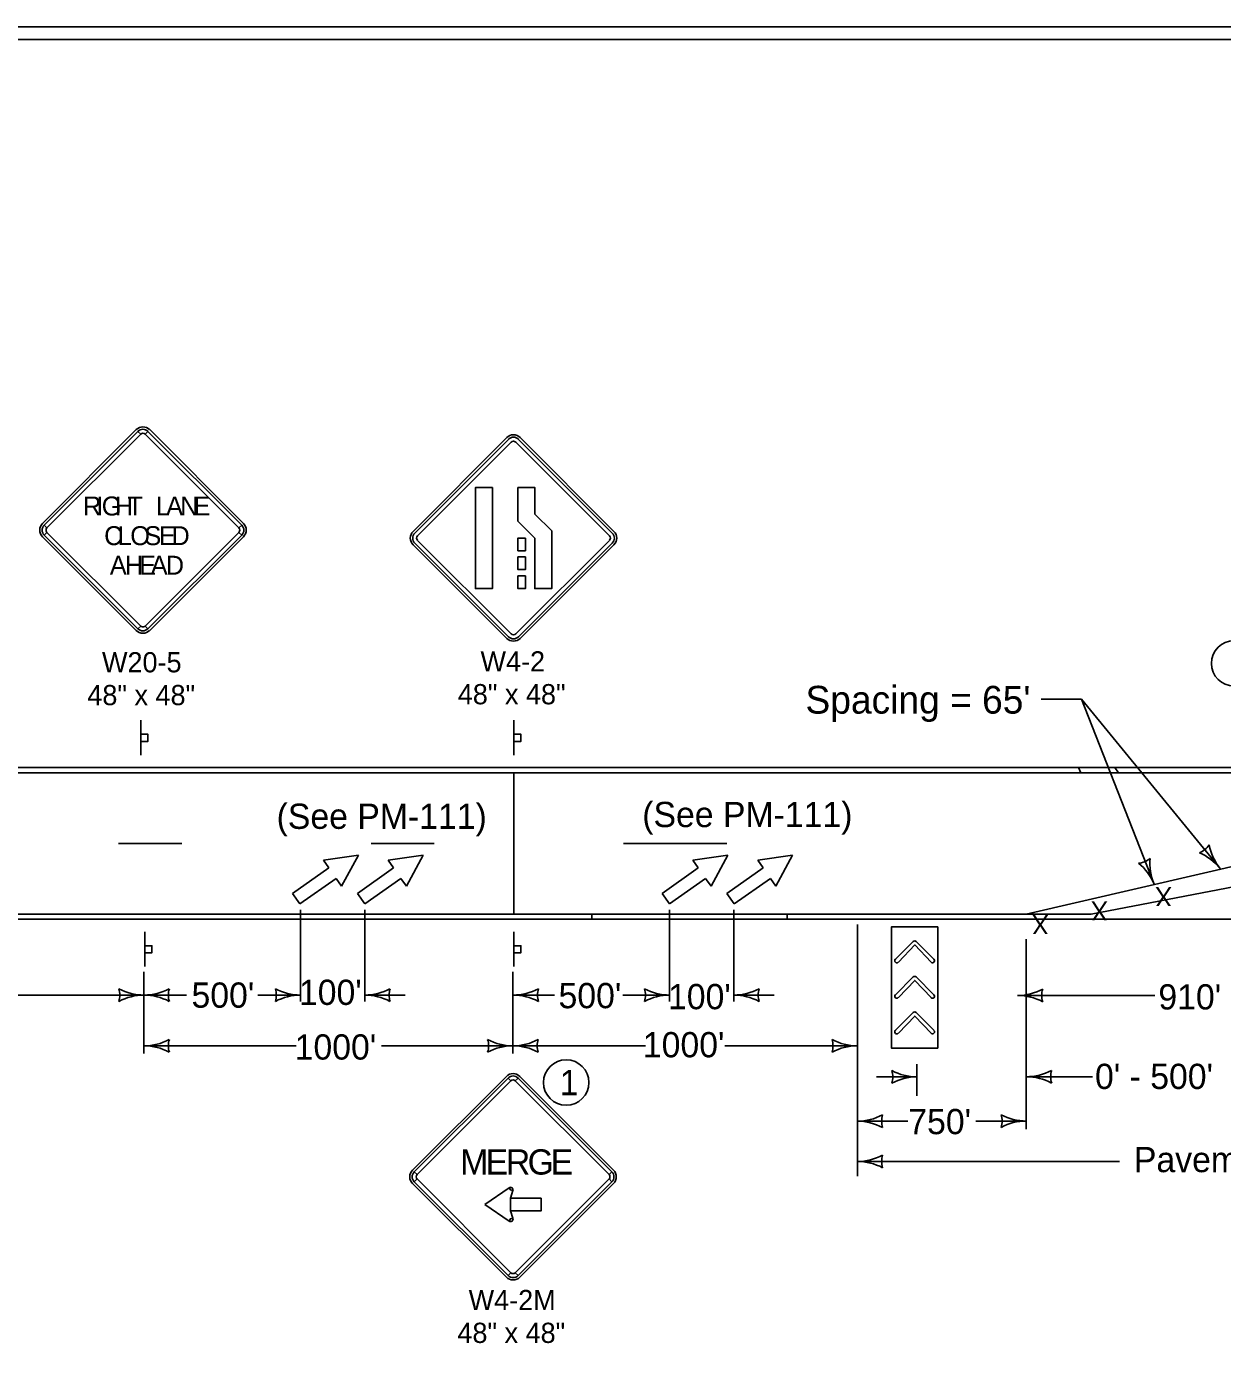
# Model space of a CAD drawing. Extents: x 10133 to 81668, y 4177 to 11018.
# Drawn here: x 28993 to 29940, y 8880 to 9944 of the extents above; entities that cross this region are included whole.
import ezdxf

# ---------------------------------------------------------------- set-up
doc = ezdxf.new("R2010")
doc.units = 0
for name, color, linetype in [('dsnNonPlotable', 7, 'Continuous'), ('dsnStdBlockModified', 7, 'Continuous'), ('dsnStdDimension', 7, 'Continuous'), ('dsnStdLabel', 7, 'Continuous'), ('dsnStdNote', 7, 'Continuous'), ('Level 12', 7, 'Continuous'), ('Level 2', 7, 'Continuous'), ('SheetBorder', 7, 'Continuous')]:
    doc.layers.add(name, color=color, linetype=linetype)

msp = doc.modelspace()

# ---------------------------------------------------------------- linework, layer by layer
at = {"layer": 'dsnNonPlotable'}
for p, q in [((29080, 9624.9), (29005.8, 9550.6)), ((29081.4, 9623.5), (29083.6, 9621.3)), ((29087.1, 9621.3), (29089.3, 9623.5)), ((29164.9, 9550.6), (29090.7, 9624.9)), ((29373.5, 9618.6), (29299.3, 9544.3)), ((29299.3, 9544.3), (29373.5, 9618.6)), ((29374.8, 9617.2), (29300.6, 9543)), ((29302.8, 9540.8), (29377, 9615)), ((29380.6, 9615), (29380.6, 9615)), ((29380.6, 9615), (29454.8, 9540.8)), ((29457, 9543), (29382.8, 9617.2)), ((29458.4, 9544.3), (29384.1, 9618.6)), ((29384.1, 9618.6), (29458.4, 9544.3)), ((29384.1, 9618.6), (29384.1, 9618.6)), ((29009.3, 9547.1), (29007.1, 9549.3)), ((29163.6, 9549.3), (29161.4, 9547.1)), ((29005.8, 9540), (29080, 9465.8)), ((29007.1, 9541.3), (29009.3, 9543.5)), ((29090.7, 9465.8), (29164.9, 9540)), ((29161.4, 9543.5), (29163.6, 9541.3)), ((29377, 9463), (29302.8, 9537.2)), ((29454.8, 9537.2), (29380.6, 9463)), ((29299.3, 9533.7), (29373.5, 9459.5)), ((29373.5, 9459.5), (29299.3, 9533.7)), ((29300.6, 9535), (29374.8, 9460.8)), ((29382.8, 9460.8), (29457, 9535)), ((29384.1, 9459.5), (29458.4, 9533.7)), ((29458.4, 9533.7), (29384.1, 9459.5)), ((29083.6, 9469.3), (29081.4, 9467.1)), ((29089.3, 9467.1), (29087.1, 9469.3)), ((29083.6, 9367.1), (29083.6, 9394.6)), ((29379, 9367.1), (29379, 9394.6)), ((29086.7, 9199.6), (29086.7, 9227.1)), ((29379, 9199.6), (29379, 9227.1)), ((29697.7, 9219.3), (29711.8, 9205.3)), ((29697.7, 9191.3), (29711.8, 9177.2)), ((29697.7, 9163), (29711.8, 9149)), ((29373.2, 9112.5), (29298.9, 9038.2)), ((29374.5, 9111.2), (29376.7, 9109)), ((29380.2, 9109), (29382.4, 9111.2)), ((29458, 9038.2), (29383.8, 9112.5)), ((29302.4, 9034.7), (29300.2, 9036.9)), ((29456.7, 9036.9), (29454.5, 9034.7)), ((29298.9, 9027.6), (29373.2, 8953.4)), ((29300.2, 9029), (29302.4, 9031.2)), ((29383.8, 8953.4), (29458, 9027.6)), ((29454.5, 9031.2), (29456.7, 9029)), ((29375.3, 9024.3), (29376.4, 9022.6)), ((29376.4, 9022.6), (29378.4, 9022)), ((29376.4, 8999.5), (29375.3, 8997.8)), ((29378.4, 9000.1), (29376.4, 8999.5)), ((29376.7, 8956.9), (29374.5, 8954.7)), ((29382.4, 8954.7), (29380.2, 8956.9))]:
    msp.add_line(p, q, dxfattribs=at)
for points in [[(29081.4, 9623.5), (29007.1, 9549.3), (29009.3, 9547.1), (29083.6, 9621.3), (29081.4, 9623.5)], [(29163.6, 9549.3), (29089.3, 9623.5), (29087.1, 9621.3), (29161.4, 9547.1), (29163.6, 9549.3)], [(29362.1, 9579), (29362.1, 9499), (29348.6, 9499), (29348.6, 9579)], [(29395.8, 9557.9), (29409.1, 9544.6), (29409.1, 9499), (29395.6, 9499), (29395.6, 9539), (29382.3, 9552.3), (29382.3, 9579), (29395.8, 9579)], [(29007.1, 9541.3), (29081.4, 9467.1), (29083.6, 9469.3), (29009.3, 9543.5), (29007.1, 9541.3)], [(29089.3, 9467.1), (29163.6, 9541.3), (29161.4, 9543.5), (29087.1, 9469.3), (29089.3, 9467.1)], [(29388.3, 9539), (29382.3, 9539), (29382.3, 9529), (29388.3, 9529)], [(29388.3, 9524), (29382.3, 9524), (29382.3, 9514), (29388.3, 9514)], [(29388.3, 9509), (29382.3, 9509), (29382.3, 9499), (29388.3, 9499)], [(29083.7, 9383.5), (29083.7, 9377.9), (29089.3, 9377.9), (29089.3, 9383.5)], [(29379.1, 9383.5), (29379.1, 9377.9), (29384.7, 9377.9), (29384.7, 9383.5)], [(29714.9, 9134.9), (29714.9, 9230.9), (29678.2, 9230.9), (29678.2, 9134.9)], [(29086.8, 9216), (29086.8, 9210.4), (29092.4, 9210.4), (29092.4, 9216)], [(29379.1, 9216), (29379.1, 9210.4), (29384.7, 9210.4), (29384.7, 9216)], [(29374.5, 9111.2), (29300.2, 9036.9), (29302.4, 9034.7), (29376.7, 9109), (29374.5, 9111.2)], [(29456.7, 9036.9), (29382.4, 9111.2), (29380.2, 9109), (29454.5, 9034.7), (29456.7, 9036.9)], [(29300.2, 9029), (29374.5, 8954.7), (29376.7, 8956.9), (29302.4, 9031.2), (29300.2, 9029)], [(29382.4, 8954.7), (29456.7, 9029), (29454.5, 9031.2), (29380.2, 8956.9), (29382.4, 8954.7)], [(29356.1, 9011.1), (29375.3, 8997.8), (29376.4, 8999.5), (29378.4, 9000.1), (29376.4, 9006.1), (29376.4, 9016.1), (29378.4, 9022), (29376.4, 9022.6), (29375.3, 9024.3), (29356.1, 9011.1)], [(29400.8, 9016.1), (29400.8, 9006.1), (29376.4, 9006.1), (29376.4, 9016.1), (29400.8, 9016.1)]]:
    msp.add_lwpolyline(points, close=True, dxfattribs=at)
for points in [[(29300.6, 9543), (29374.8, 9617.2)], [(29302.8, 9540.8), (29377, 9615)], [(29380.6, 9615), (29454.8, 9540.8)], [(29382.8, 9617.2), (29457, 9543)], [(29377, 9463), (29302.8, 9537.2)], [(29454.8, 9537.2), (29380.6, 9463)], [(29374.8, 9460.8), (29300.6, 9535)], [(29457, 9535), (29382.8, 9460.8)], [(29681.3, 9205.2), (29681.3, 9205.3), (29695.4, 9219.4), (29695.4, 9219.4)], [(29709.5, 9202.9), (29709.5, 9203), (29696.6, 9216.6), (29683.7, 9203)], [(29681.3, 9177.2), (29681.3, 9177.2), (29695.4, 9191.3), (29695.4, 9191.3)], [(29709.5, 9174.8), (29709.5, 9174.9), (29696.6, 9188.5), (29683.7, 9174.9)], [(29681.3, 9148.9), (29681.3, 9149), (29695.4, 9163.1), (29695.4, 9163.1)], [(29709.5, 9146.6), (29709.5, 9146.7), (29696.6, 9160.3), (29683.7, 9146.7)]]:
    msp.add_lwpolyline(points, dxfattribs=at)
for centre, radius, start, end in [((29085.3, 9619.6), 7.5, 45, 134.9997), ((29085.3, 9619.6), 5.62, 45, 134.9997), ((29085.3, 9619.6), 2.5, 45, 134.9997), ((29378.8, 9613.3), 7.5, 45, 134.9997), ((29378.8, 9613.3), 7.5, 45, 134.9997), ((29378.8, 9613.3), 5.63, 45, 134.9997), ((29378.8, 9613.3), 5.63, 45, 134.9997), ((29378.8, 9613.3), 2.5, 45, 134.9997), ((29378.8, 9613.3), 2.5, 45, 134.9997), ((29011.1, 9545.3), 7.5, 134.9997, 225), ((29011.1, 9545.3), 5.62, 134.9997, 225), ((29011.1, 9545.3), 2.5, 134.9997, 225), ((29159.6, 9545.3), 2.5, 315.0002, 44.9998), ((29159.6, 9545.3), 5.62, 315.0002, 44.9998), ((29159.6, 9545.3), 7.5, 315.0002, 44.9998), ((29304.6, 9539), 7.5, 134.9997, 225), ((29304.6, 9539), 7.5, 134.9997, 225), ((29304.6, 9539), 5.63, 134.9997, 225), ((29304.6, 9539), 5.63, 134.9997, 225), ((29304.6, 9539), 2.5, 134.9997, 225), ((29304.6, 9539), 2.5, 134.9997, 225), ((29453.1, 9539), 2.5, 315.0002, 44.9998), ((29453.1, 9539), 2.5, 315.0002, 44.9998), ((29453.1, 9539), 5.63, 315.0002, 44.9998), ((29453.1, 9539), 5.63, 315.0002, 44.9998), ((29453.1, 9539), 7.5, 315.0002, 44.9998), ((29453.1, 9539), 7.5, 315.0002, 44.9998), ((29085.3, 9471.1), 7.5, 225, 315.0002), ((29085.3, 9471.1), 5.62, 225, 315.0002), ((29085.3, 9471.1), 2.5, 225, 315.0002), ((29378.8, 9464.8), 2.5, 225, 315.0002), ((29378.8, 9464.8), 2.5, 225, 315.0002), ((29378.8, 9464.8), 7.5, 225, 315.0002), ((29378.8, 9464.8), 7.5, 225, 315.0002), ((29378.8, 9464.8), 5.63, 225, 315.0002), ((29378.8, 9464.8), 5.63, 225, 315.0002), ((29696.6, 9218.2), 1.65, 44.1616, 134.6098), ((29682.4, 9204.1), 1.65, 136.201, 317.3602), ((29710.7, 9204.1), 1.65, 225.0975, 45.281), ((29696.6, 9190.1), 1.65, 44.1616, 134.6098), ((29682.4, 9176), 1.65, 136.201, 317.3602), ((29710.7, 9176), 1.65, 225.0975, 45.281), ((29696.6, 9161.9), 1.65, 44.1616, 134.6098), ((29682.4, 9147.8), 1.65, 136.201, 317.3602), ((29710.7, 9147.8), 1.65, 225.0975, 45.281), ((29378.5, 9107.2), 7.5, 45, 134.9997), ((29378.5, 9107.2), 5.62, 45, 134.9997), ((29378.5, 9107.2), 2.5, 45, 134.9997), ((29304.2, 9032.9), 7.5, 134.9997, 225), ((29304.2, 9032.9), 5.62, 134.9997, 225), ((29452.7, 9032.9), 5.62, 315.0002, 44.9998), ((29452.7, 9032.9), 7.5, 315.0002, 44.9998), ((29304.2, 9032.9), 2.5, 134.9997, 225), ((29452.7, 9032.9), 2.5, 315.0002, 44.9998), ((29376.4, 9022.6), 2.03, 341.4187, 122.3124), ((29376.4, 8999.5), 2.03, 237.6875, 18.5819), ((29378.5, 8958.7), 7.5, 225, 315.0002), ((29378.5, 8958.7), 5.62, 225, 315.0002), ((29378.5, 8958.7), 2.5, 225, 315.0002)]:
    msp.add_arc(centre, radius, start, end, dxfattribs=at)
at = {"layer": 'dsnStdBlockModified'}
msp.add_lwpolyline([(28132.5, 9934), (31267.5, 9934), (31267.5, 7924), (28132.5, 7924)], close=True, dxfattribs=at)
at = {"layer": 'dsnStdDimension'}
for p, q in [((28165.7, 9357.1), (30292.4, 9357.1)), ((29955.6, 9357.1), (28165.7, 9357.1)), ((29826.4, 9357.1), (29855, 9357.1)), ((29828.1, 9353.1), (29826.4, 9357.1)), ((29855, 9357.1), (29858.1, 9353.1)), ((28161.7, 9353.1), (29379, 9353.1)), ((28161.7, 9353.1), (29957.3, 9353.1)), ((29379, 9353.1), (29379, 9241.1)), ((29957.3, 9353.1), (29379, 9353.1)), ((29379, 9353.1), (29379, 9241.1)), ((29858.1, 9353.1), (29828.1, 9353.1)), ((29836.4, 9241.1), (29992.6, 9271.1)), ((29992.6, 9271.1), (29836.4, 9241.1)), ((29210.2, 9241.1), (29210.2, 9237.1)), ((29210.2, 9237.1), (29210.2, 9241.1)), ((29210.2, 9241.1), (29261, 9241.1)), ((29502.5, 9241.1), (29261, 9241.1)), ((29261, 9241.1), (29261, 9237.1)), ((29261, 9241.1), (29261, 9237.1)), ((29379, 9241.1), (29440.8, 9241.1)), ((29440.8, 9241.1), (29595.5, 9241.1)), ((29595.5, 9241.1), (29440.8, 9241.1)), ((29440.8, 9241.1), (29440.8, 9237.1)), ((29440.8, 9237.1), (29440.8, 9241.1)), ((29440.8, 9241.1), (29595.5, 9241.1)), ((29502.5, 9237.1), (29502.5, 9241.1)), ((29595.5, 9237.1), (29595.5, 9241.1)), ((29595.5, 9241.1), (29595.5, 9237.1)), ((29595.5, 9241.1), (29836.4, 9241.1)), ((29836.4, 9241.1), (29595.5, 9241.1)), ((29595.5, 9241.1), (29595.5, 9237.1)), ((28165.7, 9237.1), (30497.9, 9237.1)), ((29210.2, 9237.1), (28165.7, 9237.1)), ((29261, 9237.1), (29210.2, 9237.1)), ((29261, 9237.1), (29502.5, 9237.1)), ((29595.5, 9237.1), (29440.8, 9237.1)), ((29440.8, 9237.1), (29595.5, 9237.1)), ((29595.5, 9237.1), (30426.1, 9237.1))]:
    msp.add_line(p, q, dxfattribs=at)
msp.add_lwpolyline([(29379, 9241.1), (29261, 9241.1), (29210.2, 9241.1)], dxfattribs=at)
at = {"layer": 'dsnStdLabel'}
for p, q in [((29785, 9241.1), (30043.8, 9300.8)), ((29256, 9287.8), (29228.3, 9283.7)), ((29228.3, 9283.7), (29232.6, 9277.6)), ((29242.6, 9263.3), (29256, 9287.8)), ((29307.3, 9287.8), (29279.6, 9283.7)), ((29279.6, 9283.7), (29283.9, 9277.6)), ((29294, 9263.3), (29307.3, 9287.8)), ((29548.6, 9287.8), (29520.9, 9283.7)), ((29520.9, 9283.7), (29525.2, 9277.6)), ((29535.3, 9263.3), (29548.6, 9287.8)), ((29599.9, 9287.8), (29572.3, 9283.7)), ((29572.3, 9283.7), (29576.6, 9277.6)), ((29586.6, 9263.3), (29599.9, 9287.8)), ((29232.6, 9277.6), (29203.9, 9257.5)), ((29283.9, 9277.6), (29255.3, 9257.5)), ((29525.2, 9277.6), (29496.6, 9257.5)), ((29576.6, 9277.6), (29547.9, 9257.5)), ((29209.7, 9249.3), (29238.3, 9269.4)), ((29238.3, 9269.4), (29242.6, 9263.3)), ((29261, 9249.3), (29289.7, 9269.4)), ((29289.7, 9269.4), (29294, 9263.3)), ((29502.3, 9249.3), (29531, 9269.4)), ((29531, 9269.4), (29535.3, 9263.3)), ((29553.6, 9249.3), (29582.3, 9269.4)), ((29582.3, 9269.4), (29586.6, 9263.3)), ((29203.9, 9257.5), (29209.7, 9249.3)), ((29255.3, 9257.5), (29261, 9249.3)), ((29496.6, 9257.5), (29502.3, 9249.3)), ((29547.9, 9257.5), (29553.6, 9249.3)), ((28169.7, 9241.1), (29785, 9241.1))]:
    msp.add_line(p, q, dxfattribs=at)
for points in [[(28161.7, 9353.1), (30191.3, 9353.1)], [(29066, 9297), (29116, 9297)], [(29266, 9297), (29316, 9297)], [(29266, 9297), (29316, 9297)], [(29465.9, 9297), (29515.9, 9297)], [(29497.7, 9297), (29547.7, 9297)]]:
    msp.add_lwpolyline(points, dxfattribs=at)
at = {"layer": 'dsnStdNote'}
for p, q in [((29796.8, 9411.3), (29828.8, 9411.3)), ((29938.5, 9277.2), (29828.8, 9411.3)), ((29886.2, 9264.9), (29828.8, 9411.3)), ((29210.2, 9244.4), (29210.2, 9171.8)), ((29261, 9244.4), (29261, 9171.8)), ((29502.5, 9244.4), (29502.5, 9171.8)), ((29553.3, 9244.4), (29553.3, 9171.8)), ((29651.2, 9232.9), (29651.2, 9033.4)), ((29785, 9221.1), (29785, 9070.7)), ((29086, 9195.3), (29086, 9130.5)), ((29378.3, 9195.3), (29378.3, 9130.5)), ((28969.6, 9176.9), (29086, 9176.9)), ((29086.8, 9176.9), (29119.8, 9176.9)), ((29176.2, 9176.9), (29210.2, 9176.9)), ((29261, 9176.9), (29293, 9176.9)), ((29379.1, 9176.9), (29411.3, 9176.9)), ((29465.5, 9176.9), (29502.5, 9176.9)), ((29553.3, 9176.9), (29585.3, 9176.9)), ((29886.8, 9176.6), (29778, 9176.6)), ((29086, 9136.7), (29206.8, 9136.7)), ((29274.3, 9136.7), (29378.3, 9136.7)), ((29483.3, 9136.7), (29378.3, 9136.7)), ((29546.1, 9136.7), (29651.1, 9136.7)), ((29698.4, 9122.3), (29698.4, 9097.2)), ((29666.4, 9112.1), (29698.4, 9112.1)), ((29837.5, 9112.2), (29785, 9112.2)), ((29651.1, 9077), (29691.1, 9077)), ((29745, 9077), (29785, 9077)), ((29858.9, 9045.1), (29651.2, 9045.1))]:
    msp.add_line(p, q, dxfattribs=at)
for centre, radius, start, end in [((29916.2, 9305), 16.4, 290.8549, 326.3216), ((29971.7, 9303.7), 42.5, 190.5158, 218.5882), ((29872.4, 9297.7), 16.4, 274.9287, 310.3954), ((29847, 9248.5), 42.5, 22.662, 50.7345), ((29925.4, 9281.2), 42.5, 174.5895, 202.662), ((29905.2, 9250.7), 42.5, 38.5882, 66.6607), ((29050.6, 9176.9), 16.4, 342.2667, 17.7334), ((29086.2, 9219.4), 42.5, 241.9275, 270), ((29086.2, 9134.4), 42.5, 90, 118.0725), ((29086.2, 9219.4), 42.5, 270, 298.0725), ((29086.2, 9134.4), 42.5, 61.9275, 90), ((29121.9, 9176.9), 16.4, 162.2666, 197.7334), ((29174.6, 9176.9), 16.4, 342.2667, 17.7334), ((29210.2, 9219.4), 42.5, 241.9275, 270), ((29210.2, 9134.4), 42.5, 90, 118.0725), ((29261, 9219.4), 42.5, 270, 298.0725), ((29261, 9134.4), 42.5, 61.9275, 90), ((29296.7, 9176.9), 16.4, 162.2666, 197.7334), ((29378.5, 9219.4), 42.5, 270, 298.0725), ((29378.5, 9134.4), 42.5, 61.9275, 90), ((29414.2, 9176.9), 16.4, 162.2666, 197.7334), ((29466.9, 9176.9), 16.4, 342.2667, 17.7334), ((29502.5, 9219.4), 42.5, 241.9275, 270), ((29502.5, 9134.4), 42.5, 90, 118.0725), ((29553.3, 9219.4), 42.5, 270, 298.0725), ((29553.3, 9134.4), 42.5, 61.9275, 90), ((29589, 9176.9), 16.4, 162.2666, 197.7334), ((29778, 9219.1), 42.5, 270, 298.0725), ((29778, 9134.1), 42.5, 61.9275, 90), ((29813.6, 9176.6), 16.4, 162.2666, 197.7334), ((29086.2, 9179.2), 42.5, 270, 298.0725), ((29086.2, 9094.2), 42.5, 61.9275, 90), ((29121.9, 9136.7), 16.4, 162.2666, 197.7334), ((29342.7, 9136.7), 16.4, 342.2667, 17.7334), ((29378.3, 9179.2), 42.5, 241.9275, 270), ((29378.3, 9094.2), 42.5, 90, 118.0725), ((29378.3, 9179.2), 42.5, 270, 298.0725), ((29378.3, 9094.2), 42.5, 61.9275, 90), ((29414, 9136.7), 16.4, 162.2666, 197.7334), ((29615.5, 9136.7), 16.4, 342.2667, 17.7334), ((29651.1, 9179.2), 42.5, 241.9275, 270), ((29651.1, 9094.2), 42.5, 90, 118.0725), ((29662.8, 9112.1), 16.4, 342.2667, 17.7334), ((29698.4, 9154.6), 42.5, 241.9275, 270), ((29698.4, 9069.6), 42.5, 90, 118.0725), ((29785, 9154.7), 42.5, 270, 298.0725), ((29785, 9069.7), 42.5, 61.9275, 90), ((29820.7, 9112.2), 16.4, 162.2666, 197.7334), ((29651.1, 9119.5), 42.5, 270, 298.0725), ((29686.8, 9077), 16.4, 162.2666, 197.7334), ((29749.4, 9077.1), 16.4, 342.2667, 17.7334), ((29785, 9119.6), 42.5, 241.9275, 270), ((29651.1, 9034.5), 42.5, 61.9275, 90), ((29785, 9034.6), 42.5, 90, 118.0725), ((29651.2, 9087.6), 42.5, 270, 298.0725), ((29686.8, 9045.1), 16.4, 162.2666, 197.7334), ((29651.2, 9002.6), 42.5, 61.9275, 90)]:
    msp.add_arc(centre, radius, start, end, dxfattribs=at)
at = {"layer": 'Level 12'}
msp.add_circle((29949.6, 9439.7), 18, dxfattribs=at)
at = {"layer": 'Level 2'}
msp.add_circle((29420.6, 9107.6), 18, dxfattribs=at)
at = {"layer": 'SheetBorder'}
msp.add_lwpolyline([(28132.5, 9944), (31267.5, 9944), (31267.5, 7924), (28132.5, 7924)], close=True, dxfattribs=at)

# ---------------------------------------------------------------- texts
at = {"layer": 'dsnNonPlotable'}
for s, height, p in [('R', 15, (29037.9, 9556.9)), ('I', 15, (29048.3, 9556.9)), ('G', 15, (29052.7, 9556.9)), ('H', 15, (29063.1, 9556.9)), ('T', 15, (29073.1, 9556.9)), ('L', 15, (29095.6, 9556.9)), ('A', 15, (29103.7, 9556.9)), ('N', 15, (29114.9, 9556.9)), ('E', 15, (29125.3, 9556.9)), ('C', 15, (29054.6, 9533.4)), ('L', 15, (29065.3, 9533.4)), ('O', 15, (29075.3, 9533.4)), ('S', 15, (29086.5, 9533.4)), ('E', 15, (29097.9, 9533.4)), ('D', 15, (29107.9, 9533.4)), ('A', 15, (29059.1, 9510)), ('H', 15, (29071, 9510)), ('E', 15, (29082.3, 9510)), ('A', 15, (29091.5, 9510)), ('D', 15, (29103.4, 9510)), ('W20-5', 16, (29052.9, 9432.6)), ('W4-2', 16, (29352.7, 9433.3)), ('48" x 48"', 16, (29041.3, 9406.6)), ('48" x 48"', 16, (29334.7, 9407.3)), ('(See PM-111)', 20, (29191.2, 9308.6)), ('(See PM-111)', 20, (29480.8, 9310)), ('M', 20, (29336.6, 9034.7)), ('E', 20, (29356.8, 9034.7)), ('R', 20, (29372.8, 9034.7)), ('G', 20, (29390, 9034.7)), ('E', 20, (29408.2, 9034.7)), ('W4-2M', 16, (29343.3, 8927.3)), ('48" x 48"', 16, (29334.4, 8901.3))]:
    msp.add_text(s, height=height, dxfattribs=at).set_placement(p)
for p in [(29900.4, 9262.5), (29849.6, 9251.1), (29802.8, 9240.4)]:
    msp.add_text('X', height=15, rotation=180, dxfattribs=at).set_placement(p)
at = {"layer": 'dsnStdNote'}
for s, height, p in [("Spacing = 65'", 22, (29610.1, 9399.9)), ("500'", 20, (29123.8, 9166.9)), ("100'", 20, (29208.9, 9169.1)), ("500'", 20, (29414.5, 9166.5)), ("100'", 20, (29501.2, 9165.7)), ("910'", 20, (29889.6, 9165.5)), ("1000'", 20, (29205.5, 9125.8)), ("1000'", 20, (29481.3, 9127.6)), ("0' - 500'", 20, (29839.4, 9102.5)), ("750'", 20, (29691.5, 9066.7)), ('Pavement Marking Removal Limits', 20, (29870.2, 9036.6))]:
    msp.add_text(s, height=height, dxfattribs=at).set_placement(p)
at = {"layer": 'Level 2'}
msp.add_text('1', height=20, dxfattribs=at).set_placement((29415.4, 9097.6))

doc.saveas('drawing.dxf')
